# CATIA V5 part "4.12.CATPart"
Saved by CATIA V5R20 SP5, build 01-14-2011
Part number: 螺母特征参数化建模
Bounding box of the stored display mesh (mm): x -30 to 30, y -30 to 30, z 0 to 20
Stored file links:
  E:\scc\4.12.CATPart
  E:\scc\DesignTable1.xls
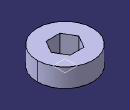
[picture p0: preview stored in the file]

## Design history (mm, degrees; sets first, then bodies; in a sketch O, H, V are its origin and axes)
Parameters
  `边长` = 15 mm {design table}
  `内孔半径` = 30 mm {design table}
  `柱高` = 28 mm {design table}
Body1 (main body)
  Sketch1 on xy-plane, origin (0, 0, 0), H (1, 0, 0), V (0, 1, 0)
    point P1 (-7.5, -12.9904)
    point P2 (7.5, -12.9904)
    point P3 (15, 0)
    point P4 (7.5, 12.9904)
    point P5 (-7.5, 12.9904)
    point P6 (-15, 0)
    point P7 (0, -12.9904)
    line L1 (-7.5, -12.9904) -> (7.5, -12.9904)
    line L2 (7.5, -12.9904) -> (15, 0)
    line L3 (15, 0) -> (7.5, 12.9904)
    line L4 (7.5, 12.9904) -> (-7.5, 12.9904)
    line L5 (-7.5, 12.9904) -> (-15, 0)
    line L6 (-15, 0) -> (-7.5, -12.9904)
    construction line L7 (0, 0) -> (0, -12.9904)
    construction circle A1 centre (0, 0) radius 15
    construction arc A2 centre (-7.5, 12.9904) radius 15 from (7.5, 12.9904) to (-15, 0) cw
    construction arc A3 centre (7.5, -12.9904) radius 15 from (15, 0) to (-7.5, -12.9904) ccw
    circle A4 centre (0, 0) radius 30
    radius A1 = 15 {= `边长`}
    radius A4 = 30 {= `内孔半径`}
    vertical: L7 V
    coincidence: A1 P1, A1 P2, A1 P3, A1 P4, A1 P5, A1 P6, A2 O, A3 O
    midpoint: P7 L1
    parallelism: L1 L4
  Pad1: profile Sketch1, direction (0, 0, 1), length 20
Relations
  design table, configuration 2, drives `边长`, `内孔半径`, `柱高`
  Pad1.FirstLimit.Length = `柱高` (deactivated)
  rule (deactivated):
    /*规则 创建者Student 2019-4-12*/
    if  `内孔半径` > `边长` *sin(60deg )
    Message ( "参数输入正确")
    else
    { Message( "请重新输入参数`边长` `内孔半径` `柱高`" ) }
  check:
    /*检查 创建者Student 2019-4-12*/
    `边长` > `内孔半径`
